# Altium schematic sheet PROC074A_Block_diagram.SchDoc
size 431 x 279 mm; Date: Not shown in title block; ApprovedBy: Not shown in title block; CheckedBy: Not shown in title block; Author: Not shown in title block; CompanyName: Not shown in title block; Engineer: Not shown in title block; Organization: Not shown in title block; Address1: Not shown in title block; Address2: Not shown in title block; Address3: Not shown in title block; Address4: Not shown in title block; DocumentNumber: 1; Revision: Use project parameter SCH_Rev; SheetNumber: 1; SheetTotal: 22; PageSetup: Record=PageOptions¦CenterHorizontal=True¦CenterVertical=True¦PrintScale=1.00¦XCorrection=1.00¦YCorrection=1.00¦PrintKind=0¦BorderSize=5000000¦LeftOffset=0¦BottomOffset=0¦Orientation=2¦PaperLength=1000¦PaperWidth=1000¦Scale=100¦PaperSource=15¦PrintQuality=600¦MediaType=1¦DitherType=10¦PaperKind=Letter¦PrintScaleMode=1
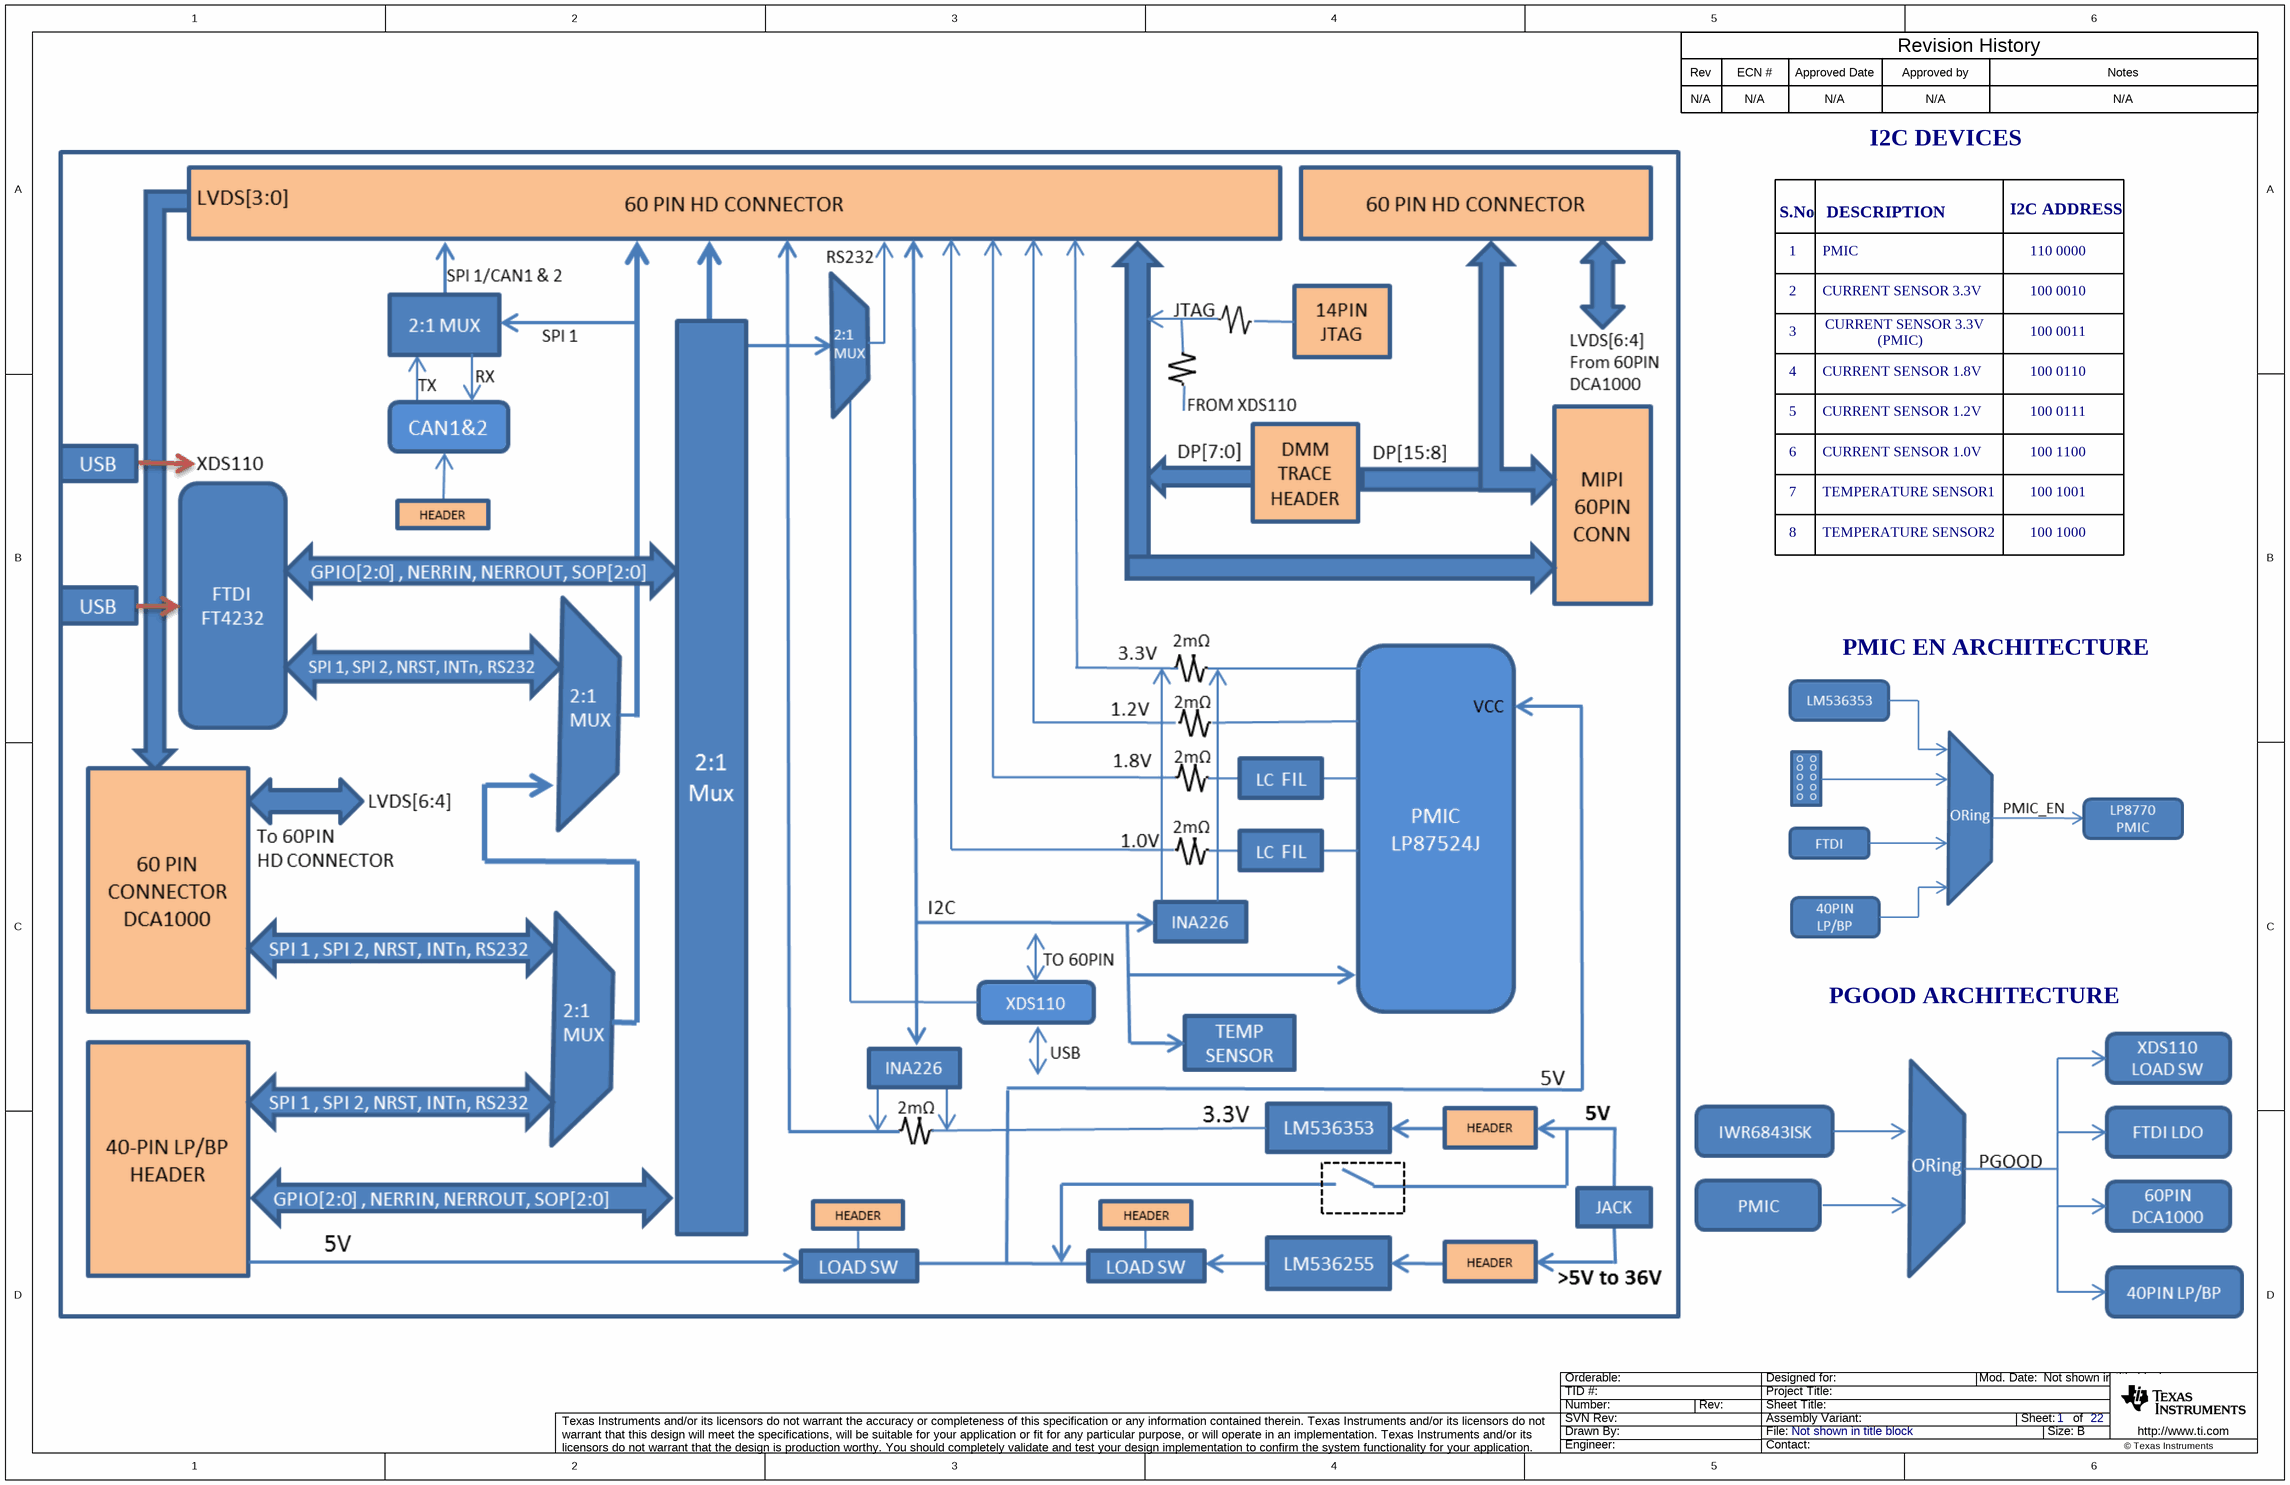
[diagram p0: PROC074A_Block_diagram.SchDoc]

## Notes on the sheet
- Rev
- N/A
- ECN #
- Approved Date
- Approved by
- Revision History
- Notes
- I2C DEVICES
- S.No
- DESCRIPTION
- I2C ADDRESS
- 1
- 2
- PMIC
- CURRENT SENSOR 3.3V
- 100 0010
- 110 0000
- 3
- (PMIC)
- 100 0011
- 4
- 5
- CURRENT SENSOR 1.8V
- CURRENT SENSOR 1.2V
- 100 0110
- 100 0111
- 6
- 7
- CURRENT SENSOR 1.0V
- TEMPERATURE SENSOR1
- 100 1100
- 100 1001
- 8
- TEMPERATURE SENSOR2
- 100 1000
- PMIC EN ARCHITECTURE
- PGOOD ARCHITECTURE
